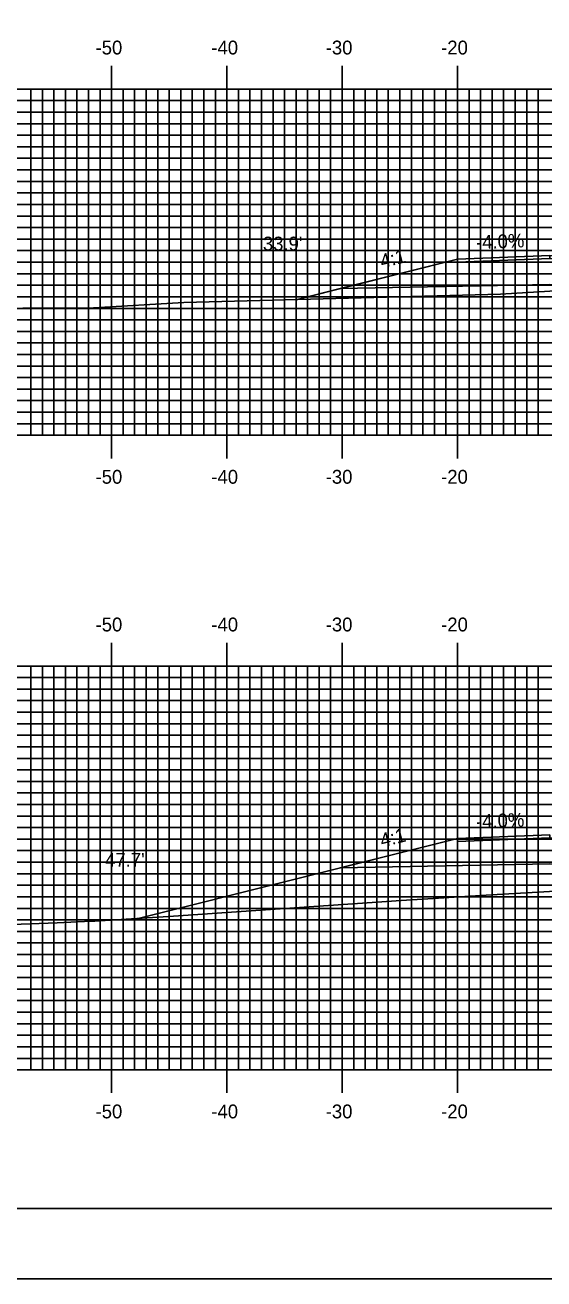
# Model space of a CAD drawing. Extents: x 853316 to 853659, y 364785 to 365005.
# Drawn here: x 853424.3 to 853469.3, y 364785.1 to 364893.8 of the extents above; entities that cross this region are included whole.
import ezdxf

# ---------------------------------------------------------------- set-up
doc = ezdxf.new("R2010")
doc.units = 0
for name, color, linetype in [('ANNOTATION', 7, 'Continuous'), ('BORDER', 7, 'Continuous'), ('D_Roadway_Centerline', 7, 'Continuous'), ('D_Roadway_Edge_Shoulder', 7, 'Continuous'), ('D_Roadway_SlopeLines', 7, 'Continuous'), ('D_Roadway_SubGrade', 7, 'Continuous'), ('D_Text_Standard', 7, 'Continuous'), ('H_V ANNOTATION', 7, 'Continuous'), ('MAJOR', 7, 'Continuous'), ('MINOR', 7, 'Continuous'), ('PLOT BOUNDARY', 7, 'Continuous'), ('S_Roadway_Centerline', 7, 'Continuous')]:
    doc.layers.add(name, color=color, linetype=linetype)

msp = doc.modelspace()

# ---------------------------------------------------------------- linework, layer by layer
at = {"layer": 'BORDER'}
msp.add_lwpolyline([(853332.16, 364791.23), (853652.16, 364791.23), (853652.16, 365001.23), (853332.16, 365001.23)], close=True, dxfattribs=at)
at = {"layer": 'D_Roadway_Centerline'}
msp.add_lwpolyline([(853447.85, 364870), (853451.58, 364870.94), (853461.76, 364873.48), (853469.76, 364873.8), (853481.76, 364873.58), (853493.76, 364873.36), (853501.76, 364873.04), (853511.93, 364870.49), (853515.93, 364869.49), (853522.19, 364872.62), (853523.44, 364873.18), (853524.69, 364873.59), (853525.94, 364873.87), (853527.19, 364874)], dxfattribs=at)
at = {"layer": 'D_Roadway_Edge_Shoulder'}
for points in [[(853469.76, 364873.8), (853461.76, 364873.48), (853461.76, 364873.23), (853469.76, 364873.55)], [(853469.76, 364823.6), (853461.76, 364823.28), (853461.76, 364823.03), (853469.76, 364823.35)]]:
    msp.add_lwpolyline(points, close=True, dxfattribs=at)
at = {"layer": 'D_Roadway_SlopeLines'}
for points in [[(853461.76, 364873.48), (853447.85, 364870)], [(853461.76, 364823.28), (853434.08, 364816.36)]]:
    msp.add_lwpolyline(points, dxfattribs=at)
at = {"layer": 'D_Roadway_SubGrade'}
for points in [[(853469.76, 364871.3), (853451.58, 364870.94), (853461.76, 364873.48), (853461.76, 364873.23), (853469.76, 364873.55), (853481.76, 364873.33), (853493.76, 364873.11), (853501.76, 364872.79), (853501.76, 364873.04), (853511.93, 364870.49), (853493.76, 364870.86), (853481.76, 364871.08)], [(853469.76, 364821.1), (853451.58, 364820.74), (853461.76, 364823.28), (853461.76, 364823.03), (853469.76, 364823.35), (853481.76, 364823.01), (853493.76, 364822.66), (853501.76, 364822.34), (853501.76, 364822.59), (853512.66, 364819.86), (853493.76, 364820.41), (853481.76, 364820.76)]]:
    msp.add_lwpolyline(points, close=True, dxfattribs=at)
at = {"layer": 'MAJOR'}
for p, q in [((853431.76, 364890.24), (853431.76, 364888.23)), ((853441.76, 364890.24), (853441.76, 364888.23)), ((853451.76, 364890.24), (853451.76, 364888.23)), ((853461.76, 364890.24), (853461.76, 364888.23)), ((853341.76, 364888.23), (853621.76, 364888.23)), ((853341.76, 364888.23), (853621.76, 364888.23)), ((853431.76, 364858.23), (853431.76, 364888.23)), ((853441.76, 364858.23), (853441.76, 364888.23)), ((853451.76, 364858.23), (853451.76, 364888.23)), ((853461.76, 364858.23), (853461.76, 364888.23)), ((853341.76, 364883.23), (853621.76, 364883.23)), ((853341.76, 364878.23), (853621.76, 364878.23)), ((853341.76, 364873.23), (853621.76, 364873.23)), ((853341.76, 364868.23), (853621.76, 364868.23)), ((853341.76, 364863.23), (853621.76, 364863.23)), ((853341.76, 364858.23), (853621.76, 364858.23)), ((853341.76, 364858.23), (853621.76, 364858.23)), ((853431.76, 364856.23), (853431.76, 364858.23)), ((853441.76, 364856.23), (853441.76, 364858.23)), ((853451.76, 364856.23), (853451.76, 364858.23)), ((853461.76, 364856.23), (853461.76, 364858.23)), ((853431.76, 364840.24), (853431.76, 364838.23)), ((853441.76, 364840.24), (853441.76, 364838.23)), ((853451.76, 364840.24), (853451.76, 364838.23)), ((853461.76, 364840.24), (853461.76, 364838.23)), ((853341.76, 364838.23), (853621.76, 364838.23)), ((853341.76, 364838.23), (853621.76, 364838.23)), ((853431.76, 364803.23), (853431.76, 364838.23)), ((853441.76, 364803.23), (853441.76, 364838.23)), ((853451.76, 364803.23), (853451.76, 364838.23)), ((853461.76, 364803.23), (853461.76, 364838.23)), ((853341.76, 364833.23), (853621.76, 364833.23)), ((853341.76, 364828.23), (853621.76, 364828.23)), ((853341.76, 364823.23), (853621.76, 364823.23)), ((853341.76, 364818.23), (853621.76, 364818.23)), ((853341.76, 364813.23), (853621.76, 364813.23)), ((853341.76, 364808.23), (853621.76, 364808.23)), ((853341.76, 364803.23), (853621.76, 364803.23)), ((853341.76, 364803.23), (853621.76, 364803.23)), ((853431.76, 364801.23), (853431.76, 364803.23)), ((853441.76, 364801.23), (853441.76, 364803.23)), ((853451.76, 364801.23), (853451.76, 364803.23)), ((853461.76, 364801.23), (853461.76, 364803.23))]:
    msp.add_line(p, q, dxfattribs=at)
at = {"layer": 'MINOR'}
for p, q in [((853424.76, 364858.23), (853424.76, 364888.23)), ((853425.76, 364858.23), (853425.76, 364888.23)), ((853426.76, 364858.23), (853426.76, 364888.23)), ((853427.76, 364858.23), (853427.76, 364888.23)), ((853428.76, 364858.23), (853428.76, 364888.23)), ((853429.76, 364858.23), (853429.76, 364888.23)), ((853430.76, 364858.23), (853430.76, 364888.23)), ((853432.76, 364858.23), (853432.76, 364888.23)), ((853433.76, 364858.23), (853433.76, 364888.23)), ((853434.76, 364858.23), (853434.76, 364888.23)), ((853435.76, 364858.23), (853435.76, 364888.23)), ((853436.76, 364858.23), (853436.76, 364888.23)), ((853437.76, 364858.23), (853437.76, 364888.23)), ((853438.76, 364858.23), (853438.76, 364888.23)), ((853439.76, 364858.23), (853439.76, 364888.23)), ((853440.76, 364858.23), (853440.76, 364888.23)), ((853442.76, 364858.23), (853442.76, 364888.23)), ((853443.76, 364858.23), (853443.76, 364888.23)), ((853444.76, 364858.23), (853444.76, 364888.23)), ((853445.76, 364858.23), (853445.76, 364888.23)), ((853446.76, 364858.23), (853446.76, 364888.23)), ((853447.76, 364858.23), (853447.76, 364888.23)), ((853448.76, 364858.23), (853448.76, 364888.23)), ((853449.76, 364858.23), (853449.76, 364888.23)), ((853450.76, 364858.23), (853450.76, 364888.23)), ((853452.76, 364858.23), (853452.76, 364888.23)), ((853453.76, 364858.23), (853453.76, 364888.23)), ((853454.76, 364858.23), (853454.76, 364888.23)), ((853455.76, 364858.23), (853455.76, 364888.23)), ((853456.76, 364858.23), (853456.76, 364888.23)), ((853457.76, 364858.23), (853457.76, 364888.23)), ((853458.76, 364858.23), (853458.76, 364888.23)), ((853459.76, 364858.23), (853459.76, 364888.23)), ((853460.76, 364858.23), (853460.76, 364888.23)), ((853462.76, 364858.23), (853462.76, 364888.23)), ((853463.76, 364858.23), (853463.76, 364888.23)), ((853464.76, 364858.23), (853464.76, 364888.23)), ((853465.76, 364858.23), (853465.76, 364888.23)), ((853466.76, 364858.23), (853466.76, 364888.23)), ((853467.76, 364858.23), (853467.76, 364888.23)), ((853468.76, 364858.23), (853468.76, 364888.23)), ((853341.76, 364887.23), (853621.76, 364887.23)), ((853341.76, 364886.23), (853621.76, 364886.23)), ((853341.76, 364885.23), (853621.76, 364885.23)), ((853341.76, 364884.23), (853621.76, 364884.23)), ((853341.76, 364882.23), (853621.76, 364882.23)), ((853341.76, 364881.23), (853621.76, 364881.23)), ((853341.76, 364880.23), (853621.76, 364880.23)), ((853341.76, 364879.23), (853621.76, 364879.23)), ((853341.76, 364877.23), (853621.76, 364877.23)), ((853341.76, 364876.23), (853621.76, 364876.23)), ((853341.76, 364875.23), (853621.76, 364875.23)), ((853341.76, 364874.23), (853621.76, 364874.23)), ((853341.76, 364872.23), (853621.76, 364872.23)), ((853341.76, 364871.23), (853621.76, 364871.23)), ((853341.76, 364870.23), (853621.76, 364870.23)), ((853341.76, 364869.23), (853621.76, 364869.23)), ((853341.76, 364867.23), (853621.76, 364867.23)), ((853341.76, 364866.23), (853621.76, 364866.23)), ((853341.76, 364865.23), (853621.76, 364865.23)), ((853341.76, 364864.23), (853621.76, 364864.23)), ((853341.76, 364862.23), (853621.76, 364862.23)), ((853341.76, 364861.23), (853621.76, 364861.23)), ((853341.76, 364860.23), (853621.76, 364860.23)), ((853341.76, 364859.23), (853621.76, 364859.23)), ((853424.76, 364803.23), (853424.76, 364838.23)), ((853425.76, 364803.23), (853425.76, 364838.23)), ((853426.76, 364803.23), (853426.76, 364838.23)), ((853427.76, 364803.23), (853427.76, 364838.23)), ((853428.76, 364803.23), (853428.76, 364838.23)), ((853429.76, 364803.23), (853429.76, 364838.23)), ((853430.76, 364803.23), (853430.76, 364838.23)), ((853432.76, 364803.23), (853432.76, 364838.23)), ((853433.76, 364803.23), (853433.76, 364838.23)), ((853434.76, 364803.23), (853434.76, 364838.23)), ((853435.76, 364803.23), (853435.76, 364838.23)), ((853436.76, 364803.23), (853436.76, 364838.23)), ((853437.76, 364803.23), (853437.76, 364838.23)), ((853438.76, 364803.23), (853438.76, 364838.23)), ((853439.76, 364803.23), (853439.76, 364838.23)), ((853440.76, 364803.23), (853440.76, 364838.23)), ((853442.76, 364803.23), (853442.76, 364838.23)), ((853443.76, 364803.23), (853443.76, 364838.23)), ((853444.76, 364803.23), (853444.76, 364838.23)), ((853445.76, 364803.23), (853445.76, 364838.23)), ((853446.76, 364803.23), (853446.76, 364838.23)), ((853447.76, 364803.23), (853447.76, 364838.23)), ((853448.76, 364803.23), (853448.76, 364838.23)), ((853449.76, 364803.23), (853449.76, 364838.23)), ((853450.76, 364803.23), (853450.76, 364838.23)), ((853452.76, 364803.23), (853452.76, 364838.23)), ((853453.76, 364803.23), (853453.76, 364838.23)), ((853454.76, 364803.23), (853454.76, 364838.23)), ((853455.76, 364803.23), (853455.76, 364838.23)), ((853456.76, 364803.23), (853456.76, 364838.23)), ((853457.76, 364803.23), (853457.76, 364838.23)), ((853458.76, 364803.23), (853458.76, 364838.23)), ((853459.76, 364803.23), (853459.76, 364838.23)), ((853460.76, 364803.23), (853460.76, 364838.23)), ((853462.76, 364803.23), (853462.76, 364838.23)), ((853463.76, 364803.23), (853463.76, 364838.23)), ((853464.76, 364803.23), (853464.76, 364838.23)), ((853465.76, 364803.23), (853465.76, 364838.23)), ((853466.76, 364803.23), (853466.76, 364838.23)), ((853467.76, 364803.23), (853467.76, 364838.23)), ((853468.76, 364803.23), (853468.76, 364838.23)), ((853341.76, 364837.23), (853621.76, 364837.23)), ((853341.76, 364836.23), (853621.76, 364836.23)), ((853341.76, 364835.23), (853621.76, 364835.23)), ((853341.76, 364834.23), (853621.76, 364834.23)), ((853341.76, 364832.23), (853621.76, 364832.23)), ((853341.76, 364831.23), (853621.76, 364831.23)), ((853341.76, 364830.23), (853621.76, 364830.23)), ((853341.76, 364829.23), (853621.76, 364829.23)), ((853341.76, 364827.23), (853621.76, 364827.23)), ((853341.76, 364826.23), (853621.76, 364826.23)), ((853341.76, 364825.23), (853621.76, 364825.23)), ((853341.76, 364824.23), (853621.76, 364824.23)), ((853341.76, 364822.23), (853621.76, 364822.23)), ((853341.76, 364821.23), (853621.76, 364821.23)), ((853341.76, 364820.23), (853621.76, 364820.23)), ((853341.76, 364819.23), (853621.76, 364819.23)), ((853341.76, 364817.23), (853621.76, 364817.23)), ((853341.76, 364816.23), (853621.76, 364816.23)), ((853341.76, 364815.23), (853621.76, 364815.23)), ((853341.76, 364814.23), (853621.76, 364814.23)), ((853341.76, 364812.23), (853621.76, 364812.23)), ((853341.76, 364811.23), (853621.76, 364811.23)), ((853341.76, 364810.23), (853621.76, 364810.23)), ((853341.76, 364809.23), (853621.76, 364809.23)), ((853341.76, 364807.23), (853621.76, 364807.23)), ((853341.76, 364806.23), (853621.76, 364806.23)), ((853341.76, 364805.23), (853621.76, 364805.23)), ((853341.76, 364804.23), (853621.76, 364804.23))]:
    msp.add_line(p, q, dxfattribs=at)
at = {"layer": 'PLOT BOUNDARY'}
msp.add_lwpolyline([(853315.97, 364785.11), (853655.97, 364785.11), (853655.97, 365005.11), (853315.97, 365005.11)], close=True, dxfattribs=at)
at = {"layer": 'S_Roadway_Centerline'}
for points in [[(853341.76, 364865.84), (853356.16, 364866.46), (853366.14, 364866.68), (853382.04, 364867.48), (853382.97, 364867.53), (853404.92, 364868.62), (853417.92, 364869.21), (853430.2, 364869.26), (853438.03, 364869.75), (853465.49, 364870.45), (853470.73, 364870.78), (853484.26, 364871.97), (853500.06, 364872.67), (853501.84, 364872.73), (853506.29, 364872.95), (853515.89, 364873.45), (853518.86, 364873.58), (853529.02, 364874.09), (853536.1, 364874.57)], [(853341.76, 364812.92), (853344.5, 364813.14), (853347.01, 364813.28), (853350.12, 364813.44), (853369.35, 364813.65), (853379.97, 364814.25), (853427.05, 364815.97), (853430, 364816.11), (853430.31, 364816.12), (853437.12, 364816.56), (853456.88, 364817.9), (853464.71, 364818.39), (853478.31, 364819.19), (853505.33, 364821.12), (853514.36, 364821.74), (853514.96, 364821.79), (853516.88, 364822.05), (853540.71, 364825.86)]]:
    msp.add_lwpolyline(points, dxfattribs=at)

# ---------------------------------------------------------------- texts
at = {"layer": 'ANNOTATION'}
for s, rotation, p in [('-4.0%', 2.2906, (853463.39, 364874.35)), ('4:1', 14.0362, (853455.21, 364872.7)), ('-4.0%', 2.2906, (853463.39, 364824.15)), ('4:1', 14.0362, (853455.21, 364822.51))]:
    msp.add_text(s, height=1.2, rotation=rotation, dxfattribs=at).set_placement(p)
at = {"layer": 'D_Text_Standard'}
for s, p in [("33.9'", (853444.88, 364874.24)), ("47.7'", (853431.2, 364820.84))]:
    msp.add_text(s, height=1.2, dxfattribs=at).set_placement(p)
at = {"layer": 'H_V ANNOTATION'}
for s, p in [('-50', (853430.37, 364891.23)), ('-40', (853440.41, 364891.23)), ('-30', (853450.33, 364891.23)), ('-20', (853460.34, 364891.23)), ('-50', (853430.37, 364854.03)), ('-40', (853440.41, 364854.03)), ('-30', (853450.33, 364854.03)), ('-20', (853460.34, 364854.03)), ('-50', (853430.37, 364841.23)), ('-40', (853440.41, 364841.23)), ('-30', (853450.33, 364841.23)), ('-20', (853460.34, 364841.23)), ('-50', (853430.37, 364799.03)), ('-40', (853440.41, 364799.03)), ('-30', (853450.33, 364799.03)), ('-20', (853460.34, 364799.03))]:
    msp.add_text(s, height=1.2, dxfattribs=at).set_placement(p)

doc.saveas('drawing.dxf')
